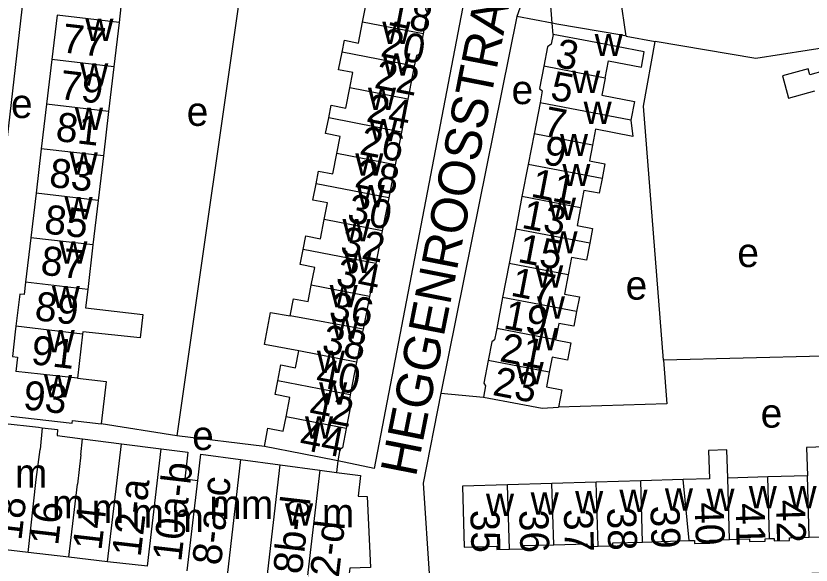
# Model space of a CAD drawing. Extents: x 161258 to 163262, y 380749 to 382054.
# Drawn here: x 162318.8 to 162428.3, y 381217.9 to 381293.5 of the extents above; entities that cross this region are included whole.
import ezdxf

# ---------------------------------------------------------------- set-up
doc = ezdxf.new("R2010")
doc.units = 0
for name, color, linetype in [('BLT_Basislijn', 7, 'Continuous'), ('BLT_Bebouwing', 7, 'Continuous'), ('BLT_Centroide', 7, 'Continuous'), ('BLT_Huisnummer', 7, 'Continuous'), ('BLT_Huisnummer_ tussenligend', 7, 'Continuous'), ('BLT_Huisnummer_reeks', 7, 'Continuous'), ('BLT_Onderverdeling_panden', 7, 'Continuous'), ('BLT_Straatnaam', 7, 'Continuous')]:
    doc.layers.add(name, color=color, linetype=linetype)

msp = doc.modelspace()

# ---------------------------------------------------------------- linework, layer by layer
at = {"layer": 'BLT_Basislijn'}
for p, q in [((162402.85, 381290.77), (162401.73, 381298.84)), ((162392.68, 381292.55), (162392.3, 381297.77)), ((162387.83, 381293.45), (162377.35, 381241.55)), ((162392.68, 381292.55), (162387.83, 381293.45)), ((162392.8, 381290.99), (162392.68, 381292.55)), ((162402.85, 381290.77), (162406.85, 381290.02)), ((162377.35, 381241.55), (162383.23, 381241.03)), ((162341.01, 381235.68), (162330.58, 381237.35)), ((162353.05, 381234.21), (162341.01, 381235.68)), ((162363.15, 381232.24), (162362.98, 381230.64))]:
    msp.add_line(p, q, dxfattribs=at)
for points in [[(162333.77, 381362.06), (162327.65, 381363.04), (162327.49, 381362.81), (162324.77, 381339.11), (162311.57, 381224.14), (162311.63, 381220.74), (162314.97, 381220.26)], [(162353.89, 381359.7), (162373.57, 381357.57), (162373.89, 381357.26), (162376.24, 381339.11), (162381.11, 381301.49), (162381, 381298.21), (162368.16, 381231.2), (162363.15, 381232.24)], [(162382.88, 381338.9), (162386.59, 381308.76), (162388.21, 381297.56), (162388.23, 381294.6), (162387.83, 381293.45)], [(162351.28, 381309.97), (162350.82, 381304.5), (162341.01, 381235.68)], [(162402.85, 381290.77), (162402.28, 381290.88), (162393.32, 381292.43), (162392.68, 381292.55)], [(162408.03, 381246.1), (162405.25, 381281.1), (162406.85, 381290.02)], [(162431.32, 381289.35), (162420.71, 381287.66), (162406.85, 381290.02)], [(162377.35, 381241.55), (162374.93, 381229.15), (162375.77, 381216.02), (162376.51, 381215.48), (162459.91, 381217.55), (162459.91, 381232.85), (162455.78, 381247.6)], [(162439.81, 381243.36), (162433.08, 381241.77), (162431.59, 381241.85), (162430.62, 381245.34), (162429.95, 381246.65), (162408.03, 381246.1)], [(162408.03, 381246.1), (162408.48, 381240.1), (162393.57, 381239.65)]]:
    msp.add_lwpolyline(points, dxfattribs=at)
at = {"layer": 'BLT_Bebouwing'}
for p, q in [((162333.76, 381298.79), (162333.04, 381292.66)), ((162324.5, 381293.65), (162323.78, 381287.52)), ((162333.04, 381292.66), (162332.32, 381286.52)), ((162323.78, 381287.52), (162323.06, 381281.38)), ((162332.32, 381286.52), (162331.6, 381280.39)), ((162373.69, 381286.6), (162372.81, 381282.07)), ((162323.06, 381281.38), (162322.34, 381275.25)), ((162372.81, 381282.07), (162371.93, 381277.54)), ((162391.01, 381281.58), (162390.18, 381277.3)), ((162331.6, 381280.39), (162330.89, 381274.25)), ((162371.93, 381277.54), (162371.05, 381273.01)), ((162390.18, 381277.3), (162389.38, 381273.09)), ((162322.34, 381275.25), (162321.62, 381269.11)), ((162330.89, 381274.25), (162330.17, 381268.11)), ((162371.05, 381273.01), (162370.17, 381268.48)), ((162389.38, 381273.09), (162388.52, 381268.64)), ((162321.62, 381269.11), (162320.9, 381262.98)), ((162370.17, 381268.48), (162369.29, 381263.95)), ((162388.52, 381268.64), (162387.67, 381264.16)), ((162330.17, 381268.11), (162329.45, 381261.98)), ((162369.29, 381263.95), (162368.4, 381259.42)), ((162387.67, 381264.16), (162386.76, 381259.45)), ((162320.9, 381262.98), (162320.18, 381256.85)), ((162329.45, 381261.98), (162328.73, 381255.84)), ((162368.4, 381259.42), (162367.52, 381254.89)), ((162386.76, 381259.45), (162385.86, 381254.76)), ((162367.52, 381254.89), (162366.64, 381250.36)), ((162385.86, 381254.76), (162385.04, 381250.47)), ((162328.02, 381249.71), (162327.31, 381243.64)), ((162365.76, 381245.84), (162364.88, 381241.31)), ((162328.02, 381235.27), (162333.4, 381234.58)), ((162333.4, 381234.58), (162338.86, 381233.87)), ((162349.78, 381232.42), (162355.23, 381231.69)), ((162355.23, 381231.69), (162360.68, 381230.95)), ((162422.38, 381230.02), (162416.86, 381229.86)), ((162427.83, 381230.18), (162422.38, 381230.02)), ((162392.65, 381229.13), (162386.55, 381228.95)), ((162398.76, 381229.31), (162392.65, 381229.13)), ((162404.87, 381229.5), (162398.76, 381229.31)), ((162410.74, 381229.67), (162404.87, 381229.5)), ((162405.12, 381221.05), (162411.53, 381221.24)), ((162320.51, 381219.61), (162314.97, 381220.26)), ((162326.13, 381218.96), (162320.51, 381219.61)), ((162331.45, 381218.34), (162326.13, 381218.96)), ((162336.94, 381217.71), (162331.45, 381218.34))]:
    msp.add_line(p, q, dxfattribs=at)
for points in [[(162366.56, 381292.69), (162367.05, 381295.2), (162365.07, 381295.58), (162365.46, 381297.59)], [(162375.46, 381295.65), (162375.22, 381294.46), (162375.49, 381294.06), (162374.91, 381291.07)], [(162363.75, 381288.53), (162364.07, 381290.19), (162366, 381289.81), (162366.56, 381292.69)], [(162374.91, 381291.07), (162374.36, 381288.23), (162373.98, 381288.1), (162373.69, 381286.6)], [(162392.8, 381290.99), (162392.54, 381289.63), (162392.05, 381289.3), (162391.54, 381286.61)], [(162399.99, 381284.99), (162400.44, 381287.36), (162404.97, 381286.49), (162405.37, 381288.58), (162397.71, 381290.05), (162392.8, 381290.99)], [(162431.32, 381289.35), (162432.09, 381286.51), (162428.15, 381285.44), (162427.93, 381286.24), (162424.39, 381285.28), (162425.23, 381282.19), (162428.86, 381283.2)], [(162364.82, 381283.62), (162365.24, 381285.75), (162363.28, 381286.13), (162363.75, 381288.53)], [(162391.54, 381286.61), (162390.95, 381283.54), (162391.32, 381283.22), (162391.01, 381281.58)], [(162399.99, 381284.99), (162399.54, 381282.63), (162404, 381281.77), (162403.5, 381279.18)], [(162361.92, 381279.49), (162362.25, 381281.23), (162364.28, 381280.84), (162364.82, 381283.62)], [(162363.05, 381274.57), (162363.51, 381276.93), (162361.49, 381277.32), (162361.92, 381279.49)], [(162403.5, 381279.18), (162403.8, 381276.93), (162398.63, 381277.93), (162398.22, 381275.75)], [(162398.22, 381275.75), (162397.8, 381273.58), (162399.94, 381273.17), (162399.55, 381271.14)], [(162360.17, 381270.42), (162360.51, 381272.16), (162362.5, 381271.77), (162363.05, 381274.57)], [(162361.28, 381265.51), (162361.73, 381267.78), (162359.74, 381268.17), (162360.17, 381270.42)], [(162399.55, 381271.14), (162399.16, 381269.1), (162397.06, 381269.51), (162396.6, 381267.08)], [(162396.6, 381267.08), (162396.14, 381264.66), (162398.25, 381264.26), (162397.86, 381262.21)], [(162358.41, 381261.36), (162358.77, 381263.24), (162360.77, 381262.85), (162361.28, 381265.51)], [(162397.86, 381262.21), (162397.41, 381259.88), (162395.35, 381260.27), (162394.89, 381257.88)], [(162359.51, 381256.45), (162359.98, 381258.88), (162358, 381259.27), (162358.41, 381261.36)], [(162394.89, 381257.88), (162394.38, 381255.22), (162396.44, 381254.82), (162396.05, 381252.8)], [(162320.18, 381256.85), (162319.98, 381255.15), (162319.36, 381255.22), (162318.85, 381250.78)], [(162356.61, 381252.21), (162357.07, 381254.58), (162359.07, 381254.19), (162359.51, 381256.45)], [(162328.73, 381255.84), (162328.44, 381253.3), (162336.32, 381252.38), (162335.94, 381249.17), (162328.05, 381250), (162328.02, 381249.71)], [(162357.8, 381247.38), (162353.05, 381248.26), (162353.91, 381252.69), (162356.61, 381252.21)], [(162396.05, 381252.8), (162395.66, 381250.79), (162393.58, 381251.18), (162393.35, 381250), (162393.14, 381248.91)], [(162318.85, 381250.78), (162318.75, 381250), (162318.36, 381246.62), (162319.06, 381246.54), (162318.84, 381244.56)], [(162366.64, 381250.36), (162366.57, 381250), (162365.76, 381245.84)], [(162385.04, 381250.47), (162384.95, 381250), (162384.74, 381248.89), (162384.37, 381248.64), (162383.88, 381246.07)], [(162393.14, 381248.91), (162395.23, 381248.51), (162394.77, 381246.1), (162392.66, 381246.51), (162392.27, 381244.47)], [(162354.89, 381243.24), (162355.32, 381245.45), (162357.35, 381245.06), (162357.8, 381247.38)], [(162383.88, 381246.07), (162383.28, 381242.93), (162383.52, 381242.57), (162383.23, 381241.03)], [(162392.27, 381244.47), (162391.88, 381242.42), (162394.03, 381242.01), (162393.57, 381239.65)], [(162327.31, 381243.64), (162331.26, 381243.18), (162330.58, 381237.35)], [(162356.05, 381238.32), (162356.56, 381240.97), (162354.53, 381241.37), (162354.89, 381243.24)], [(162364.88, 381241.31), (162364.66, 381240.17), (162364.93, 381239.78), (162364.33, 381236.71)], [(162383.23, 381241.03), (162388.14, 381240.09), (162391.3, 381239.49), (162393.57, 381239.65)], [(162318.13, 381238.41), (162326.58, 381237.44), (162326.63, 381237.81), (162330.58, 381237.35)], [(162353.05, 381234.21), (162353.54, 381236.72), (162355.66, 381236.31), (162356.05, 381238.32)], [(162316.96, 381237.44), (162321.93, 381236.86), (162322.46, 381236.8)], [(162322.46, 381236.8), (162324.59, 381236.55), (162324.5, 381235.73), (162328.02, 381235.27)], [(162364.33, 381236.71), (162363.81, 381234.02), (162363.45, 381233.78), (162363.15, 381232.24)], [(162338.86, 381233.87), (162342.5, 381233.41), (162342.08, 381229.76), (162343.9, 381229.55)], [(162363.15, 381232.24), (162358.24, 381233.19), (162353.05, 381234.21)], [(162416.86, 381229.86), (162416.74, 381233.75), (162414.22, 381233.67), (162414.34, 381229.78), (162410.74, 381229.67)], [(162433.35, 381230.35), (162430.36, 381230.26), (162430.25, 381234.15), (162427.71, 381234.07), (162427.83, 381230.18)], [(162343.9, 381229.55), (162344.32, 381233.16), (162349.78, 381232.42)], [(162362.98, 381230.64), (162366.29, 381230.2), (162365.96, 381227.35), (162367.22, 381227.34), (162367.68, 381217.54), (162364.8, 381217.44), (162364.47, 381214.53), (162358.85, 381215.16)], [(162360.68, 381230.95), (162362.98, 381230.64)], [(162386.55, 381228.95), (162380.32, 381228.76), (162380.57, 381220.32), (162385.07, 381220.46), (162385.08, 381220), (162386.81, 381220.05)], [(162411.53, 381221.24), (162412.28, 381221.26), (162412.29, 381220.84), (162414.38, 381220.9), (162414.37, 381221.31), (162417.11, 381221.39)], [(162417.11, 381221.39), (162419.86, 381221.47), (162419.87, 381221.1), (162422.02, 381221.16), (162422.01, 381221.51), (162422.62, 381221.53)], [(162422.62, 381221.53), (162423.23, 381221.55), (162423.24, 381221.21), (162425.36, 381221.27), (162425.35, 381221.64), (162428.08, 381221.72)], [(162428.08, 381221.72), (162430.81, 381221.8), (162430.82, 381221.39), (162432.7, 381221.45), (162432.69, 381221.83), (162433.6, 381221.85)], [(162386.81, 381220.05), (162388.71, 381220.1), (162388.7, 381220.56), (162392.9, 381220.68)], [(162392.9, 381220.68), (162397.45, 381220.82), (162397.46, 381220.41), (162399.02, 381220.46)], [(162399.02, 381220.46), (162401.03, 381220.52), (162401.02, 381220.93), (162405.12, 381221.05)]]:
    msp.add_lwpolyline(points, dxfattribs=at)
at = {"layer": 'BLT_Onderverdeling_panden'}
for p, q in [((162333.04, 381292.66), (162324.5, 381293.65)), ((162374.91, 381291.07), (162366.56, 381292.69)), ((162373.69, 381286.6), (162363.75, 381288.53)), ((162332.32, 381286.52), (162323.78, 381287.52)), ((162399.99, 381284.99), (162391.54, 381286.61)), ((162372.81, 381282.07), (162364.82, 381283.62)), ((162331.6, 381280.39), (162323.06, 381281.38)), ((162403.5, 381279.18), (162391.01, 381281.58)), ((162371.93, 381277.54), (162361.92, 381279.49)), ((162398.22, 381275.75), (162390.18, 381277.3)), ((162330.89, 381274.25), (162322.34, 381275.25)), ((162371.05, 381273.01), (162363.05, 381274.57)), ((162399.55, 381271.14), (162389.38, 381273.09)), ((162370.17, 381268.48), (162360.17, 381270.42)), ((162330.17, 381268.11), (162321.62, 381269.11)), ((162396.6, 381267.08), (162388.52, 381268.64)), ((162369.29, 381263.95), (162361.28, 381265.51)), ((162397.86, 381262.21), (162387.67, 381264.16)), ((162329.45, 381261.98), (162320.9, 381262.98)), ((162368.4, 381259.42), (162358.41, 381261.36)), ((162394.89, 381257.88), (162386.76, 381259.45)), ((162328.73, 381255.84), (162320.18, 381256.85)), ((162367.52, 381254.89), (162359.51, 381256.45)), ((162396.05, 381252.8), (162385.86, 381254.76)), ((162366.64, 381250.36), (162356.61, 381252.21)), ((162328.02, 381249.71), (162318.85, 381250.78)), ((162393.14, 381248.91), (162385.04, 381250.47)), ((162365.76, 381245.84), (162357.8, 381247.38)), ((162392.27, 381244.47), (162383.88, 381246.07)), ((162327.31, 381243.64), (162318.84, 381244.56)), ((162364.88, 381241.31), (162354.89, 381243.24)), ((162364.33, 381236.71), (162356.05, 381238.32)), ((162322.46, 381236.8), (162322.17, 381233.82)), ((162327.77, 381233.08), (162328.02, 381235.27)), ((162331.45, 381218.34), (162333.4, 381234.58)), ((162321.64, 381229.66), (162322.17, 381233.82)), ((162336.94, 381217.71), (162338.86, 381233.87)), ((162327.77, 381233.08), (162327.3, 381229)), ((162349.78, 381232.42), (162347.92, 381216.43)), ((162353.39, 381215.8), (162355.23, 381231.69)), ((162360.68, 381230.95), (162358.85, 381215.16)), ((162422.62, 381221.53), (162422.38, 381230.02)), ((162428.08, 381221.72), (162427.83, 381230.18)), ((162320.51, 381219.61), (162321.64, 381229.66)), ((162326.13, 381218.96), (162327.3, 381229)), ((162342.43, 381217.07), (162343.9, 381229.55)), ((162386.81, 381220.05), (162386.55, 381228.95)), ((162392.9, 381220.68), (162392.65, 381229.13)), ((162399.02, 381220.46), (162398.76, 381229.31)), ((162405.12, 381221.05), (162404.87, 381229.5)), ((162411.53, 381221.24), (162410.74, 381229.67)), ((162417.11, 381221.39), (162416.86, 381229.86))]:
    msp.add_line(p, q, dxfattribs=at)

# ---------------------------------------------------------------- texts
at = {"layer": 'BLT_Centroide'}
for s, p in [('w', (162328.41, 381290.09)), ('w', (162369.3, 381289.66)), ('w', (162398.53, 381288)), ('w', (162369.3, 381285.31)), ('w', (162327.69, 381283.94)), ('w', (162395.43, 381282.91)), ('w', (162367.32, 381280.59)), ('e', (162387.09, 381281.39)), ('e', (162318.16, 381279.47)), ('e', (162342.36, 381278.39)), ('w', (162397.01, 381278.66)), ('w', (162326.97, 381277.81)), ('w', (162367.52, 381276.25)), ('w', (162393.76, 381274.22)), ('w', (162326.25, 381271.69)), ('w', (162365.57, 381271.53)), ('w', (162394.08, 381270.09)), ('w', (162365.77, 381267.19)), ('w', (162325.54, 381265.53)), ('w', (162392.09, 381265.41)), ('w', (162363.81, 381262.47)), ('w', (162392.32, 381260.81)), ('w', (162324.82, 381259.41)), ('e', (162418.18, 381258.94)), ('w', (162363.99, 381258.12)), ('w', (162390.34, 381256.12)), ('e', (162402.8, 381254.45)), ('w', (162323.79, 381253.28)), ('w', (162362.04, 381253.41)), ('w', (162390.58, 381251.84)), ('w', (162362.26, 381249.06)), ('w', (162323.07, 381247.19)), ('w', (162389.59, 381247.47)), ('w', (162360.29, 381244.34)), ('w', (162387.66, 381242.78)), ('w', (162322.71, 381241)), ('w', (162360.59, 381239.97)), ('e', (162421.39, 381236.81)), ('w', (162358.65, 381235.28)), ('e', (162343.11, 381233.73)), ('m', (162318.72, 381228.52)), ('w', (162383.56, 381224.64)), ('w', (162389.72, 381224.81)), ('w', (162395.84, 381225)), ('w', (162401.94, 381225.17)), ('w', (162408.2, 381225.36)), ('w', (162413.92, 381225.33)), ('w', (162419.75, 381225.7)), ('w', (162425.22, 381225.69)), ('m', (162323.81, 381224.31)), ('m', (162329.28, 381223.69)), ('m', (162345.47, 381224.24)), ('m', (162349.82, 381224.24)), ('m', (162334.78, 381223.05)), ('m', (162340.27, 381222.41)), ('w', (162355.89, 381223.29)), ('m', (162360.97, 381223.06))]:
    msp.add_text(s, height=4, dxfattribs=at).set_placement(p)
at = {"layer": 'BLT_Huisnummer'}
for s, rotation, p in [('18', 349.0216, (162369.88, 381292.33)), ('3', 349.1344, (162392.95, 381286.56)), ('22', 349.0183, (162368.05, 381283.65)), ('79', 353.3337, (162324.71, 381282.12)), ('7', 349.1287, (162391.28, 381277.19)), ('26', 349.0196, (162366.01, 381274.51)), ('83', 353.3351, (162323.3, 381270.01)), ('11', 349.123, (162389.6, 381268.64)), ('30', 349.018, (162364.31, 381265.18)), ('15', 349.133, (162387.8, 381259.66)), ('87', 353.3294, (162322.12, 381257.92)), ('34', 349.0174, (162362.74, 381256.35)), ('19', 349.1543, (162385.83, 381250.53)), ('38', 349.0182, (162360.81, 381247.16)), ('23', 349.153, (162384.34, 381241.33)), ('93', 353.4321, (162319.72, 381239.36)), ('44', 349.0002, (162357.72, 381233.86)), ('18', 83.375, (162319.59, 381221.17)), ('42', 271.6541, (162423.48, 381226.82)), ('16', 83.375, (162324.65, 381220.48)), ('38', 271.6466, (162400.24, 381225.76)), ('39', 271.6509, (162406.2, 381226.03)), ('40', 271.6497, (162412.3, 381226.49)), ('41', 271.6485, (162417.92, 381226.36)), ('35', 271.7102, (162381.4, 381225.46)), ('36', 271.7102, (162388.14, 381225.44)), ('37', 271.6478, (162394.28, 381225.56))]:
    msp.add_text(s, height=4, rotation=rotation, dxfattribs=at).set_placement(p)
at = {"layer": 'BLT_Huisnummer_ tussenligend'}
for s, rotation, p in [('77', 353.3314, (162325.03, 381288.55)), ('20', 349.0216, (162368.91, 381288.01)), ('5', 349.1344, (162392.27, 381282.06)), ('24', 349.0183, (162366.95, 381279.01)), ('81', 353.3337, (162324.2, 381276.34)), ('9', 349.1287, (162391.28, 381273.18)), ('28', 349.0196, (162365.34, 381270)), ('85', 353.3351, (162322.62, 381263.6)), ('13', 349.123, (162388.34, 381264.36)), ('32', 349.018, (162363.36, 381260.68)), ('17', 349.133, (162386.83, 381255.02)), ('89', 353.3294, (162321.31, 381251.64)), ('36', 349.0174, (162361.79, 381251.7)), ('21', 349.1543, (162385.31, 381245.99)), ('91', 353.3294, (162320.81, 381245.58)), ('40', 349.0182, (162359.98, 381242.52)), ('42', 349.0182, (162359.04, 381238.01)), ('14', 83.375, (162330.61, 381219.8))]:
    msp.add_text(s, height=4, rotation=rotation, dxfattribs=at).set_placement(p)
at = {"layer": 'BLT_Huisnummer_reeks'}
for s, rotation, p in [('10a-b', 83.3743, (162341.6, 381218.25)), ('8-a-c', 83.3743, (162347.06, 381217.73)), ('12-a', 83.375, (162336.01, 381218.9)), ('8b-d', 83.3743, (162358.2, 381216.51)), ('2-d', 83.3743, (162363.29, 381216.08))]:
    msp.add_text(s, height=4, rotation=rotation, dxfattribs=at).set_placement(p)
at = {"layer": 'BLT_Straatnaam'}
msp.add_text('HEGGENROOSSTRAAT', height=5, rotation=78.8081, dxfattribs=at).set_placement((162373.91, 381229.9))

doc.saveas('drawing.dxf')
